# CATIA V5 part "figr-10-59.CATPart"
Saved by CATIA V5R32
Part number: Part1
Bounding box of the stored display mesh (mm): x -322.306 to 0, y -118.205 to 88.531, z 0 to 101.949
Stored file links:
  D:\PROJECTS\Project 2022\CATIA V5 6R 2022\Resources\Part Files\c10_catia_v5_6r2022_prt\c10_catia_v5_6r2022_prt\figr-10-59.CATPart
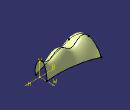
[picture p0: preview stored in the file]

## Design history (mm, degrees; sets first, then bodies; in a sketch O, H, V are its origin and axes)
Set1
  Curve1: Elements (vertex of Sketch2; vertex of Sketch1; vertex of Sketch3)
  Curve2: Elements (Sketch2.P2; vertex of Sketch1; Sketch3.P2)
  Loft1: Sections (Curve2; Sketch4), Guides (Sketch2; Sketch1; Sketch3)
Body1 (main body)
  Sketch1 on zx-plane, origin (0, 0, 0), H (-1, 0, 0), V (0, 0, 1)
    spline S1 through (0, 96.336) (70.1946, 72.4244) (144.1119, 96.336) (203.5098, 63.985) (253.668, 92.1163) (322.3056, 72.4244)
    point P1 (0, 96.336)
    coincidence: P1 V
  Sketch2 on xy-plane, origin (0, 0, 0), H (1, 0, 0), V (0, 1, 0)
    point P1 (0, 47.0553)
    point P2 (-315.9706, 88.5306)
    arc A1 centre (-78.7604, 671.3501) radius 629.2433 from (0, 47.0553) to (-315.9706, 88.5306) cw
    coincidence: P1 V
  Sketch3 on xy-plane, origin (0, 0, 0), H (1, 0, 0), V (0, 1, 0)
    line L1 (0, -26.5991) -> (-311.8959, -118.2048)
    point P1 (0, -26.5991)
    point P2 (-311.8959, -118.2048)
    coincidence: P1 V
  Sketch4 on yz-plane, origin (0, 0, 0), H (0, 1, 0), V (0, 0, 1)
    point P1 (-26.5991, 0)
    point P2 (0, 58.544)
    point P3 (47.0553, 0)
    reference projected point E1 (47.0553, 0) from vertex of Sketch2
    reference projected point E2 (-26.5991, 0) from vertex of Sketch3
    spline S1 through (-26.5991, 0) (-29.9268, 35.6209) (0, 96.336) (47.0553, 0)
    reference projected point E3 (0, 96.336) from vertex of Sketch1
    point P4 (-26.5991, 0)
    point P5 (0, 96.336)
    point P6 (47.0553, 0)
    coincidence: P1 H, P3 H, E1 P3, P1 E2, P4 P1, P5 V, P6 P3, E3 S1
